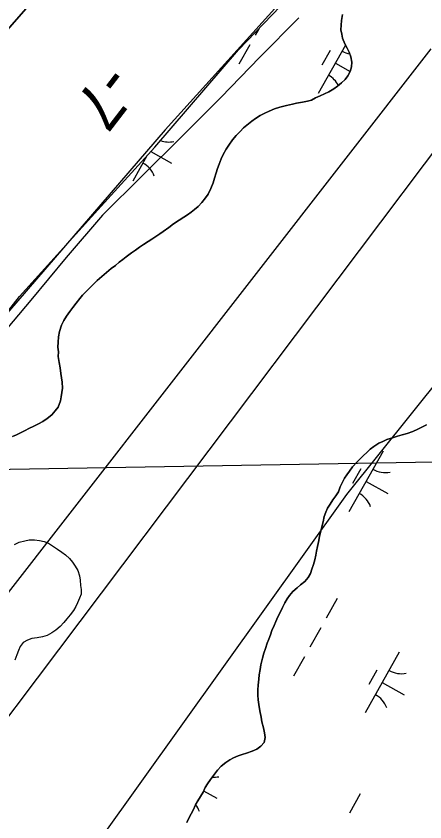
# Model space of a CAD drawing. Extents: x 3913936 to 3933962, y 195330 to 217741.
# Drawn here: x 3922654 to 3922947, y 199333 to 199912 of the extents above; entities that cross this region are included whole.
import ezdxf

# ---------------------------------------------------------------- set-up
doc = ezdxf.new("R2010")
doc.units = 0
for name, color, linetype in [('V-GRID-MAJR', 7, 'Continuous'), ('V-RIVR-EDGE', 7, 'Continuous'), ('V-RIVR-RANG', 7, 'Continuous'), ('V-RRAP-FSHR', 7, 'Continuous'), ('V-TOPO-DPTH', 7, 'Continuous'), ('V-TOPO-MINR', 7, 'Continuous'), ('V-TOPO-SHOR', 7, 'Continuous'), ('V-UTIL-LINE', 7, 'Continuous'), ('V-WETL-SWMP', 7, 'Continuous')]:
    doc.layers.add(name, color=color, linetype=linetype)

msp = doc.modelspace()

# ---------------------------------------------------------------- linework, layer by layer
at = {"layer": 'V-GRID-MAJR'}
msp.add_spline([(3918580.26, 199515.41), (3920000.19, 199540.18), (3925326.04, 199633.54), (3926654.92, 199656.95)], degree=3, dxfattribs=at)
at = {"layer": 'V-RIVR-EDGE'}
msp.add_lwpolyline([(3922915.85, 200002.09), (3922760.82, 199830.21), (3922588.94, 199631.37), (3922578.83, 199608.9), (3922568.72, 199595.42), (3922495.7, 199516.78), (3922437.28, 199431.4), (3922350.78, 199337.04), (3922232.82, 199213.46), (3922129.47, 199055.06)], dxfattribs=at)
at = {"layer": 'V-RRAP-FSHR'}
msp.add_lwpolyline([(3922856.72, 199910.69), (3922828.81, 199882.43), (3922800.8, 199853.48), (3922772.41, 199825.3), (3922744.18, 199797.13), (3922715.63, 199768.95), (3922689.57, 199738.64), (3922664.23, 199707.86), (3922638.48, 199677.79), (3922612.93, 199646.3), (3922588.47, 199614.66), (3922564.3, 199582.79), (3922540.12, 199550.92), (3922515.95, 199519.51), (3922491.29, 199487.57), (3922465.58, 199456.93), (3922439.87, 199426.28), (3922414.17, 199395.64), (3922387.94, 199365.43), (3922361.51, 199335.42), (3922335.68, 199305.4)], dxfattribs=at)
at = {"layer": 'V-TOPO-DPTH'}
msp.add_lwpolyline([(3923572.36, 200998.52), (3923503.91, 200907.2), (3923435.27, 200816.03), (3923326.2, 200671.67), (3923311.77, 200652.93), (3923297.12, 200634.37), (3923282.13, 200616.08), (3923266.93, 200597.97), (3923166.97, 200481.11), (3923101.22, 200405.05), (3923034.94, 200329.46), (3922967.87, 200254.57), (3922900.28, 200180.15), (3922705.27, 199967.65), (3922675.93, 199934.9), (3922647.14, 199901.69), (3922619.17, 199867.8), (3922591.73, 199833.44), (3922552.62, 199783.23), (3922506.1, 199723.37), (3922459.66, 199663.45), (3922413.34, 199603.44), (3922367.1, 199543.37), (3922084.4, 199175.27)], dxfattribs=at)
at = {"layer": 'V-TOPO-MINR'}
msp.add_lwpolyline([(3922084.4, 199175.27), (3922367.1, 199543.37), (3922413.34, 199603.44), (3922459.66, 199663.45), (3922506.1, 199723.37), (3922552.62, 199783.23), (3922591.73, 199833.44), (3922619.17, 199867.8), (3922647.14, 199901.69), (3922675.93, 199934.9), (3922705.27, 199967.65), (3922900.28, 200180.15), (3922967.87, 200254.57), (3923034.94, 200329.46), (3923101.22, 200405.05), (3923166.97, 200481.11), (3923266.93, 200597.97), (3923282.13, 200616.08), (3923297.12, 200634.37), (3923311.77, 200652.93), (3923326.2, 200671.67), (3923435.27, 200816.03), (3923503.91, 200907.2), (3923572.36, 200998.52)], dxfattribs=at)
at = {"layer": 'V-TOPO-SHOR'}
for points in [[(3922703.51, 199713.67), (3922706.1, 199716.36), (3922708.86, 199719.23), (3922711.79, 199722.09), (3922715.16, 199724.95), (3922718.61, 199727.9), (3922721.98, 199730.6), (3922725.09, 199732.94), (3922727.76, 199735.2), (3922730.18, 199737.11), (3922732.77, 199739.02), (3922736.57, 199741.88), (3922739.33, 199743.88), (3922742.36, 199745.88), (3922745.2, 199747.79), (3922748.57, 199750.05), (3922751.08, 199751.7), (3922753.93, 199753.53), (3922756.86, 199755.61), (3922759.37, 199757.35), (3922763.34, 199760.21), (3922766.79, 199762.82), (3922770.68, 199765.34), (3922774.05, 199767.43), (3922776.81, 199769.25), (3922779.4, 199771.08), (3922781.82, 199773.07), (3922784.32, 199775.15), (3922787.08, 199778.1), (3922789.58, 199781.4), (3922791.48, 199784.09), (3922793.54, 199788.07), (3922795.09, 199792.14), (3922796.21, 199795.61), (3922797.32, 199799.42), (3922798.35, 199802.45), (3922799.38, 199805.48), (3922801.01, 199809.38), (3922802.48, 199812.58), (3922804.45, 199816.31), (3922806.35, 199819.17), (3922809.11, 199822.98), (3922811.78, 199826.19), (3922814.54, 199829.14), (3922817.04, 199831.57), (3922820.5, 199834.52), (3922823, 199836.52), (3922825.5, 199838.34), (3922828.96, 199840.6), (3922832.24, 199842.17), (3922835.52, 199843.56), (3922839.33, 199845.39), (3922843.13, 199846.53), (3922847.8, 199847.75), (3922852.21, 199848.71), (3922855.15, 199849.33), (3922859.39, 199850.12), (3922862.85, 199850.82), (3922865.87, 199851.52), (3922868.81, 199853.17), (3922872.09, 199854.74), (3922875.29, 199856.05), (3922878.4, 199857.61), (3922881.85, 199859.61), (3922884.62, 199861.52), (3922887.38, 199863.87), (3922889.97, 199866.47), (3922891.95, 199868.9), (3922893.59, 199872.02), (3922894.53, 199875.48), (3922894.78, 199878.94), (3922894.08, 199882.66), (3922892.94, 199886.03), (3922891.55, 199888.8), (3922889.9, 199891.9), (3922888.16, 199895.97), (3922887.54, 199898.91), (3922887.01, 199902.02), (3922887.09, 199905.31), (3922887.43, 199908.86), (3922888.11, 199913.1)], [(3922650.94, 199610.14), (3922653.79, 199611.27), (3922656.73, 199612.66), (3922660.1, 199614.4), (3922662.77, 199615.88), (3922666.23, 199617.36), (3922669.77, 199619.1), (3922672.71, 199620.75), (3922675.9, 199622.84), (3922679.19, 199625.61), (3922681.77, 199628.39), (3922683.75, 199631.16), (3922685.47, 199635.58), (3922686.07, 199638.61), (3922686.58, 199641.64), (3922686.83, 199644.76), (3922686.65, 199649.08), (3922686.21, 199652.11), (3922685.85, 199655.31), (3922685.15, 199659.37), (3922684.53, 199663.09), (3922683.91, 199667.5), (3922683.99, 199670.88), (3922683.64, 199674.25), (3922683.71, 199677.71), (3922684.13, 199681.61), (3922684.81, 199685.42), (3922686.27, 199690.01), (3922687.82, 199693.21), (3922689.89, 199696.51), (3922692.22, 199699.8), (3922694.46, 199702.75), (3922696.7, 199705.7), (3922699.46, 199709.08), (3922701.35, 199711.42), (3922703.51, 199713.67)], [(3922948.46, 199618.49), (3922945.69, 199616.93), (3922942.23, 199615.19), (3922938.6, 199613.53), (3922934.63, 199612.22), (3922930.91, 199611.35), (3922927.54, 199610.39), (3922924, 199609.17), (3922920.02, 199607.86), (3922917.17, 199606.55), (3922914.14, 199605.16), (3922910.6, 199602.81), (3922908.1, 199600.82), (3922905.6, 199598.56), (3922903.27, 199596.48), (3922901.11, 199594.31), (3922898.87, 199592.05), (3922895.33, 199588.15), (3922893.18, 199585.2), (3922891.28, 199582.51), (3922889.56, 199580), (3922888, 199577.31), (3922886.37, 199573.85), (3922885.17, 199570.38), (3922883.36, 199567.44), (3922881.21, 199564.49), (3922879.31, 199561.54), (3922877.42, 199558.68), (3922876.04, 199555.65), (3922875.01, 199552.62), (3922874.16, 199548.72), (3922873.3, 199545.09), (3922872.53, 199542.06), (3922871.68, 199538.51), (3922870.99, 199535.39), (3922870.23, 199531.15), (3922869.54, 199527.77), (3922868.95, 199524.74), (3922868.26, 199521.45), (3922867.23, 199518.16), (3922866.03, 199514.7), (3922865, 199511.67), (3922863.37, 199508.72), (3922861.04, 199506.03), (3922858.02, 199503.51), (3922855.51, 199501.34), (3922852.41, 199498.65), (3922850.08, 199495.96), (3922848.35, 199493.45), (3922846.63, 199490.68), (3922845, 199487.3), (3922843.28, 199483.75), (3922841.73, 199480.63), (3922840.18, 199477.16), (3922838.98, 199474.39), (3922837.43, 199470.67), (3922836.4, 199467.72), (3922835.28, 199464.52), (3922834.08, 199461.66), (3922832.71, 199457.76), (3922831.59, 199454.39), (3922830.56, 199450.83), (3922829.54, 199445.99), (3922828.86, 199442.61), (3922828.26, 199438.8)], [(3922652.37, 199532.49), (3922655.91, 199534.06), (3922659.8, 199535.2), (3922663.08, 199535.72), (3922666.71, 199535.9), (3922670.43, 199535.4), (3922673.71, 199534.63), (3922676.91, 199533.34), (3922680.55, 199531.02), (3922683.32, 199529.12), (3922686.35, 199526.97), (3922689.03, 199524.99), (3922691.89, 199522.41), (3922694.23, 199519.73), (3922696.14, 199516.98), (3922697.88, 199513.78), (3922699.1, 199510.07), (3922699.63, 199506.79), (3922699.98, 199503.16), (3922700.42, 199500.14), (3922700.43, 199496.77), (3922699.14, 199494), (3922697.68, 199490.62), (3922696.48, 199487.86), (3922694.85, 199485.08), (3922692.52, 199482.05), (3922690.02, 199479.02), (3922687.79, 199476.42), (3922685.2, 199473.57), (3922682.1, 199470.96), (3922679.25, 199469.06), (3922675.97, 199467.23), (3922672.69, 199466.27), (3922668.81, 199465.57), (3922664.83, 199464.87), (3922661.9, 199463.82), (3922658.62, 199462), (3922656.46, 199459.23), (3922655.26, 199456.46), (3922654.24, 199453.17), (3922652.78, 199449.54)], [(3922828.26, 199438.8), (3922827.92, 199435.68), (3922827.42, 199431.44), (3922827.25, 199428.24), (3922827.18, 199424.26), (3922827.53, 199420.89), (3922827.97, 199417.6), (3922828.68, 199413.11), (3922829.64, 199408.52), (3922830.26, 199405.24), (3922831.31, 199400.91), (3922832.01, 199397.28), (3922832.54, 199393.99), (3922831.77, 199390.27), (3922829.44, 199387.67), (3922826.51, 199385.5), (3922823.31, 199384.02), (3922819.25, 199382.62), (3922816.14, 199381.66), (3922813.2, 199380.7), (3922809.83, 199379.4), (3922807.06, 199377.83), (3922804.21, 199375.92), (3922801.02, 199373.23), (3922798.34, 199370.45), (3922795.33, 199366.64), (3922793.34, 199363.78), (3922791.19, 199360.57), (3922789.55, 199357.88), (3922787.92, 199354.76), (3922786.11, 199351.65), (3922784.21, 199348.35), (3922782.58, 199345.67), (3922780.94, 199342.29), (3922779.31, 199339.17), (3922777.93, 199336.39), (3922776.21, 199332.84)]]:
    msp.add_lwpolyline(points, dxfattribs=at)
at = {"layer": 'V-UTIL-LINE'}
for points in [[(3922259.35, 198607.65), (3922481.8, 198996.51), (3922891.23, 199568.37), (3923401.91, 200205.88), (3924391.34, 201632.88), (3925141.51, 202100.49), (3925635.89, 202689.84), (3926060.57, 203224.55), (3926266.36, 203722.12), (3926398.76, 204373.14), (3926759.45, 205211.96), (3927229.53, 206070.79), (3927602.51, 206766.2), (3928031.78, 207586.17)], [(3922166.91, 198676.44), (3922606.64, 199354.27), (3923719.03, 200830.83), (3923718.13, 200956.52)], [(3922951.57, 199888.34), (3922069.47, 198754.87)]]:
    msp.add_lwpolyline(points, dxfattribs=at)
at = {"layer": 'V-WETL-SWMP'}
for p, q in [((3922813.46, 199887.6), (3922870.99, 199947.78)), ((3922887.43, 199908.86), (3922887.09, 199905.31)), ((3922888.11, 199913.1), (3922887.43, 199908.86)), ((3922828.05, 199902.86), (3922825.48, 199898.29)), ((3922887.09, 199905.31), (3922887.02, 199902.02)), ((3922887.02, 199902.02), (3922887.54, 199898.91)), ((3922887.54, 199898.91), (3922888.16, 199895.97)), ((3922821.56, 199891.31), (3922813.72, 199877.37)), ((3922890.32, 199891.12), (3922870.74, 199856.3)), ((3922888.16, 199895.97), (3922889.9, 199891.91)), ((3922889.9, 199891.91), (3922891.55, 199888.8)), ((3922753.24, 199817.73), (3922813.46, 199887.6)), ((3922879.21, 199887.1), (3922873.33, 199876.64)), ((3922891.55, 199888.8), (3922892.94, 199886.03)), ((3922892.94, 199886.03), (3922894.08, 199882.66)), ((3922894.08, 199882.66), (3922894.78, 199878.94)), ((3922882.99, 199878.09), (3922893.62, 199872.12)), ((3922894.53, 199875.48), (3922893.59, 199872.02)), ((3922894.78, 199878.94), (3922894.53, 199875.48)), ((3922891.95, 199868.9), (3922889.97, 199866.47)), ((3922893.59, 199872.02), (3922891.95, 199868.9)), ((3922887.38, 199863.87), (3922884.62, 199861.52)), ((3922889.97, 199866.47), (3922887.38, 199863.87)), ((3922878.4, 199857.61), (3922875.29, 199856.05)), ((3922881.85, 199859.61), (3922878.4, 199857.61)), ((3922884.62, 199861.52), (3922881.85, 199859.61)), ((3922862.85, 199850.82), (3922859.39, 199850.12)), ((3922865.87, 199851.52), (3922862.85, 199850.82)), ((3922868.81, 199853.17), (3922865.87, 199851.52)), ((3922872.09, 199854.74), (3922868.81, 199853.17)), ((3922875.29, 199856.05), (3922872.09, 199854.74)), ((3922839.33, 199845.39), (3922835.52, 199843.56)), ((3922843.13, 199846.52), (3922839.33, 199845.39)), ((3922847.8, 199847.75), (3922843.13, 199846.52)), ((3922852.21, 199848.71), (3922847.8, 199847.75)), ((3922855.15, 199849.33), (3922852.21, 199848.71)), ((3922859.39, 199850.12), (3922855.15, 199849.33)), ((3922828.96, 199840.6), (3922825.5, 199838.34)), ((3922832.24, 199842.17), (3922828.96, 199840.6)), ((3922835.52, 199843.56), (3922832.24, 199842.17)), ((3922820.5, 199834.52), (3922817.04, 199831.57)), ((3922823, 199836.52), (3922820.5, 199834.52)), ((3922825.5, 199838.34), (3922823, 199836.52)), ((3922814.54, 199829.14), (3922811.78, 199826.19)), ((3922817.04, 199831.57), (3922814.54, 199829.14)), ((3922809.11, 199822.98), (3922806.35, 199819.17)), ((3922811.78, 199826.19), (3922809.11, 199822.98)), ((3922712.32, 199772.69), (3922753.24, 199817.73)), ((3922804.45, 199816.31), (3922802.47, 199812.58)), ((3922806.35, 199819.17), (3922804.45, 199816.31)), ((3922747.59, 199811.51), (3922737.38, 199793.34)), ((3922750.46, 199814.66), (3922765.32, 199806.31)), ((3922802.47, 199812.58), (3922801.01, 199809.38)), ((3922799.38, 199805.48), (3922798.35, 199802.45)), ((3922801.01, 199809.38), (3922799.38, 199805.48)), ((3922797.32, 199799.42), (3922796.21, 199795.61)), ((3922798.35, 199802.45), (3922797.32, 199799.42)), ((3922796.21, 199795.61), (3922795.09, 199792.14)), ((3922793.54, 199788.07), (3922791.48, 199784.09)), ((3922795.09, 199792.14), (3922793.54, 199788.07)), ((3922789.58, 199781.4), (3922787.08, 199778.11)), ((3922791.48, 199784.09), (3922789.58, 199781.4)), ((3922787.08, 199778.11), (3922784.32, 199775.15)), ((3922655.96, 199710.58), (3922712.32, 199772.69)), ((3922779.4, 199771.08), (3922776.81, 199769.25)), ((3922781.82, 199773.07), (3922779.4, 199771.08)), ((3922784.32, 199775.15), (3922781.82, 199773.07)), ((3922770.68, 199765.34), (3922766.79, 199762.82)), ((3922774.05, 199767.43), (3922770.68, 199765.34)), ((3922776.81, 199769.25), (3922774.05, 199767.43)), ((3922763.34, 199760.21), (3922759.37, 199757.35)), ((3922766.79, 199762.82), (3922763.34, 199760.21)), ((3922753.93, 199753.53), (3922751.08, 199751.7)), ((3922756.86, 199755.61), (3922753.93, 199753.53)), ((3922759.37, 199757.35), (3922756.86, 199755.61)), ((3922745.21, 199747.79), (3922742.36, 199745.88)), ((3922748.57, 199750.05), (3922745.21, 199747.79)), ((3922751.08, 199751.7), (3922748.57, 199750.05)), ((3922736.57, 199741.88), (3922732.77, 199739.02)), ((3922739.33, 199743.88), (3922736.57, 199741.88)), ((3922742.36, 199745.88), (3922739.33, 199743.88)), ((3922727.76, 199735.2), (3922725.09, 199732.94)), ((3922730.18, 199737.11), (3922727.76, 199735.2)), ((3922732.77, 199739.02), (3922730.18, 199737.11)), ((3922721.98, 199730.6), (3922718.61, 199727.9)), ((3922725.09, 199732.94), (3922721.98, 199730.6)), ((3922715.16, 199724.95), (3922711.79, 199722.09)), ((3922718.61, 199727.9), (3922715.16, 199724.95)), ((3922708.86, 199719.23), (3922706.1, 199716.36)), ((3922711.79, 199722.09), (3922708.86, 199719.23)), ((3922703.51, 199713.67), (3922701.35, 199711.42)), ((3922706.1, 199716.36), (3922703.51, 199713.67)), ((3922586.49, 199623.64), (3922655.96, 199710.58)), ((3922699.46, 199709.08), (3922696.7, 199705.7)), ((3922701.35, 199711.42), (3922699.46, 199709.08)), ((3922694.46, 199702.75), (3922692.22, 199699.8)), ((3922696.7, 199705.7), (3922694.46, 199702.75)), ((3922689.89, 199696.51), (3922687.82, 199693.21)), ((3922692.22, 199699.8), (3922689.89, 199696.51)), ((3922686.27, 199690.01), (3922684.81, 199685.42)), ((3922687.82, 199693.21), (3922686.27, 199690.01)), ((3922684.81, 199685.42), (3922684.13, 199681.61)), ((3922683.71, 199677.71), (3922683.64, 199674.25)), ((3922684.13, 199681.61), (3922683.71, 199677.71)), ((3922683.64, 199674.25), (3922683.99, 199670.88)), ((3922683.99, 199670.88), (3922683.91, 199667.5)), ((3922683.91, 199667.5), (3922684.53, 199663.09)), ((3922684.53, 199663.09), (3922685.15, 199659.37)), ((3922685.15, 199659.37), (3922685.85, 199655.31)), ((3922685.85, 199655.31), (3922686.21, 199652.11)), ((3922686.21, 199652.11), (3922686.65, 199649.08)), ((3922686.65, 199649.08), (3922686.83, 199644.76)), ((3922686.83, 199644.76), (3922686.58, 199641.64)), ((3922686.07, 199638.61), (3922685.47, 199635.58)), ((3922686.58, 199641.64), (3922686.07, 199638.61)), ((3922683.75, 199631.17), (3922681.77, 199628.39)), ((3922685.47, 199635.58), (3922683.75, 199631.17)), ((3922679.19, 199625.61), (3922675.91, 199622.84)), ((3922681.77, 199628.39), (3922679.19, 199625.61)), ((3922669.77, 199619.1), (3922666.23, 199617.36)), ((3922672.71, 199620.75), (3922669.77, 199619.1)), ((3922675.91, 199622.84), (3922672.71, 199620.75)), ((3922660.1, 199614.4), (3922656.73, 199612.66)), ((3922662.77, 199615.88), (3922660.1, 199614.4)), ((3922666.23, 199617.36), (3922662.77, 199615.88)), ((3922934.63, 199612.22), (3922938.61, 199613.53)), ((3922938.61, 199613.53), (3922942.23, 199615.19)), ((3922942.23, 199615.19), (3922945.69, 199616.93)), ((3922945.69, 199616.93), (3922948.46, 199618.49)), ((3922653.79, 199611.27), (3922650.94, 199610.14)), ((3922656.73, 199612.66), (3922653.79, 199611.27)), ((3922917.17, 199606.55), (3922920.02, 199607.86)), ((3922920.02, 199607.86), (3922924, 199609.17)), ((3922924, 199609.17), (3922927.54, 199610.39)), ((3922927.54, 199610.39), (3922930.91, 199611.35)), ((3922930.91, 199611.35), (3922934.63, 199612.22)), ((3922908.1, 199600.82), (3922910.6, 199602.81)), ((3922910.6, 199602.81), (3922914.14, 199605.16)), ((3922914.14, 199605.16), (3922917.17, 199606.55)), ((3922917.27, 199599.61), (3922892.77, 199556.03)), ((3922901.11, 199594.31), (3922903.27, 199596.48)), ((3922903.27, 199596.48), (3922905.6, 199598.56)), ((3922905.6, 199598.56), (3922908.1, 199600.82)), ((3922895.33, 199588.15), (3922898.87, 199592.05)), ((3922898.87, 199592.05), (3922901.11, 199594.31)), ((3922891.28, 199582.51), (3922893.18, 199585.2)), ((3922893.18, 199585.2), (3922895.33, 199588.15)), ((3922901.23, 199586.83), (3922895.35, 199576.37)), ((3922888.01, 199577.31), (3922889.56, 199580)), ((3922889.56, 199580), (3922891.28, 199582.51)), ((3922885.17, 199570.38), (3922886.37, 199573.85)), ((3922886.37, 199573.85), (3922888.01, 199577.31)), ((3922905.02, 199577.82), (3922920.71, 199569)), ((3922881.21, 199564.49), (3922883.36, 199567.44)), ((3922883.36, 199567.44), (3922885.17, 199570.38)), ((3922877.42, 199558.68), (3922879.31, 199561.54)), ((3922879.31, 199561.54), (3922881.21, 199564.49)), ((3922875.01, 199552.62), (3922876.04, 199555.65)), ((3922876.04, 199555.65), (3922877.42, 199558.68)), ((3922874.16, 199548.72), (3922875.01, 199552.62)), ((3922872.53, 199542.06), (3922873.3, 199545.09)), ((3922873.3, 199545.09), (3922874.16, 199548.72)), ((3922870.99, 199535.39), (3922871.68, 199538.51)), ((3922871.68, 199538.51), (3922872.53, 199542.06)), ((3922870.23, 199531.15), (3922870.99, 199535.39)), ((3922868.95, 199524.74), (3922869.54, 199527.77)), ((3922869.54, 199527.77), (3922870.23, 199531.15)), ((3922867.23, 199518.16), (3922868.26, 199521.45)), ((3922868.26, 199521.45), (3922868.95, 199524.74)), ((3922866.03, 199514.7), (3922867.23, 199518.16)), ((3922863.37, 199508.72), (3922865, 199511.67)), ((3922865, 199511.67), (3922866.03, 199514.7)), ((3922855.51, 199501.34), (3922858.02, 199503.51)), ((3922858.02, 199503.51), (3922861.04, 199506.03)), ((3922861.04, 199506.03), (3922863.37, 199508.72)), ((3922850.08, 199495.96), (3922852.41, 199498.65)), ((3922852.41, 199498.65), (3922855.51, 199501.34)), ((3922846.63, 199490.68), (3922848.35, 199493.45)), ((3922848.35, 199493.45), (3922850.08, 199495.96)), ((3922884.32, 199493.63), (3922876.48, 199479.68)), ((3922843.28, 199483.75), (3922845, 199487.3)), ((3922845, 199487.3), (3922846.63, 199490.68)), ((3922840.18, 199477.16), (3922841.73, 199480.63)), ((3922841.73, 199480.63), (3922843.28, 199483.75)), ((3922838.98, 199474.39), (3922840.18, 199477.16)), ((3922836.4, 199467.72), (3922837.43, 199470.67)), ((3922837.43, 199470.67), (3922838.98, 199474.39)), ((3922872.56, 199472.71), (3922864.72, 199458.76)), ((3922834.08, 199461.66), (3922835.28, 199464.52)), ((3922835.28, 199464.52), (3922836.4, 199467.72)), ((3922831.59, 199454.38), (3922832.71, 199457.76)), ((3922832.71, 199457.76), (3922834.08, 199461.66)), ((3922830.56, 199450.83), (3922831.59, 199454.38)), ((3922860.8, 199451.79), (3922852.96, 199437.84)), ((3922928.9, 199455.15), (3922904.4, 199411.56)), ((3922828.86, 199442.61), (3922829.54, 199445.99)), ((3922829.54, 199445.99), (3922830.56, 199450.83)), ((3922828.26, 199438.8), (3922828.86, 199442.61)), ((3922912.86, 199442.36), (3922906.98, 199431.9)), ((3922827.42, 199431.44), (3922827.92, 199435.68)), ((3922827.92, 199435.68), (3922828.26, 199438.8)), ((3922827.18, 199424.26), (3922827.25, 199428.24)), ((3922827.25, 199428.24), (3922827.42, 199431.44)), ((3922916.65, 199433.35), (3922932.34, 199424.53)), ((3922827.53, 199420.89), (3922827.18, 199424.26)), ((3922827.97, 199417.6), (3922827.53, 199420.89)), ((3922828.68, 199413.11), (3922827.97, 199417.6)), ((3922829.64, 199408.52), (3922828.68, 199413.11)), ((3922830.26, 199405.24), (3922829.64, 199408.52)), ((3922831.31, 199400.91), (3922830.26, 199405.24)), ((3922832.01, 199397.28), (3922831.31, 199400.91)), ((3922831.77, 199390.27), (3922832.54, 199393.99)), ((3922832.54, 199393.99), (3922832.01, 199397.28)), ((3922826.51, 199385.5), (3922829.44, 199387.67)), ((3922829.44, 199387.67), (3922831.77, 199390.27)), ((3922816.14, 199381.66), (3922819.25, 199382.62)), ((3922819.25, 199382.62), (3922823.31, 199384.02)), ((3922823.31, 199384.02), (3922826.51, 199385.5)), ((3922804.21, 199375.92), (3922807.06, 199377.83)), ((3922807.06, 199377.83), (3922809.83, 199379.4)), ((3922809.83, 199379.4), (3922813.2, 199380.7)), ((3922813.2, 199380.7), (3922816.14, 199381.66)), ((3922795.33, 199366.64), (3922798.34, 199370.45)), ((3922798.34, 199370.45), (3922801.02, 199373.23)), ((3922801.02, 199373.23), (3922804.21, 199375.92)), ((3922793.34, 199363.78), (3922795.33, 199366.64)), ((3922789.55, 199357.88), (3922791.19, 199360.57)), ((3922791.19, 199360.57), (3922793.34, 199363.78)), ((3922786.11, 199351.64), (3922787.92, 199354.76)), ((3922787.92, 199354.76), (3922789.55, 199357.88)), ((3922788.32, 199355.54), (3922797.74, 199350.24)), ((3922900.89, 199353.54), (3922893.05, 199339.59)), ((3922782.58, 199345.66), (3922784.21, 199348.35)), ((3922784.21, 199348.35), (3922786.11, 199351.64)), ((3922779.31, 199339.17), (3922780.94, 199342.29)), ((3922780.94, 199342.29), (3922782.58, 199345.66)), ((3922776.21, 199332.84), (3922777.93, 199336.39)), ((3922777.93, 199336.39), (3922779.31, 199339.17))]:
    msp.add_line(p, q, dxfattribs=at)
msp.add_lwpolyline([(3922652.37, 199532.49), (3922655.91, 199534.06), (3922659.8, 199535.19), (3922663.08, 199535.72), (3922666.71, 199535.9), (3922670.43, 199535.4), (3922673.71, 199534.63), (3922676.91, 199533.34), (3922680.55, 199531.02), (3922683.32, 199529.12), (3922686.35, 199526.97), (3922689.03, 199524.99), (3922691.89, 199522.41), (3922694.23, 199519.74), (3922696.14, 199516.98), (3922697.88, 199513.78), (3922699.1, 199510.07), (3922699.63, 199506.79), (3922699.98, 199503.16), (3922700.42, 199500.14), (3922700.43, 199496.77), (3922699.14, 199494), (3922697.68, 199490.62), (3922696.48, 199487.86), (3922694.85, 199485.08), (3922692.52, 199482.05), (3922690.02, 199479.02), (3922687.79, 199476.42), (3922685.2, 199473.57), (3922682.1, 199470.96), (3922679.25, 199469.06), (3922675.97, 199467.23), (3922672.69, 199466.27), (3922668.81, 199465.57), (3922664.83, 199464.87), (3922661.9, 199463.82), (3922658.62, 199462), (3922656.46, 199459.23), (3922655.26, 199456.46), (3922654.24, 199453.17), (3922652.78, 199449.54)], dxfattribs=at)
for centre, start, end in [((3922896.74, 199902.05), 239.88608, 258.99604), ((3922869.67, 199853.9), 27.66759, 61.42973), ((3922763.37, 199839.09), 250.10972, 281.42974), ((3922736.3, 199790.94), 19.88608, 61.42973), ((3922918.76, 199601.78), 239.88608, 281.42974), ((3922891.69, 199553.63), 19.88608, 61.42973), ((3922930.39, 199457.31), 239.88608, 281.42974), ((3922903.32, 199409.16), 19.88608, 61.42973), ((3922795.79, 199383.02), 265.81119, 281.42974), ((3922768.72, 199334.87), 19.88608, 37.97877)]:
    msp.add_arc(centre, 17.62, start, end, dxfattribs=at)

# ---------------------------------------------------------------- texts
at = {"layer": 'V-RIVR-RANG'}
msp.add_text('-7', height=33.5, rotation=232.44833, dxfattribs=at).set_placement((3922717.41, 199879.16))

doc.saveas('drawing.dxf')
